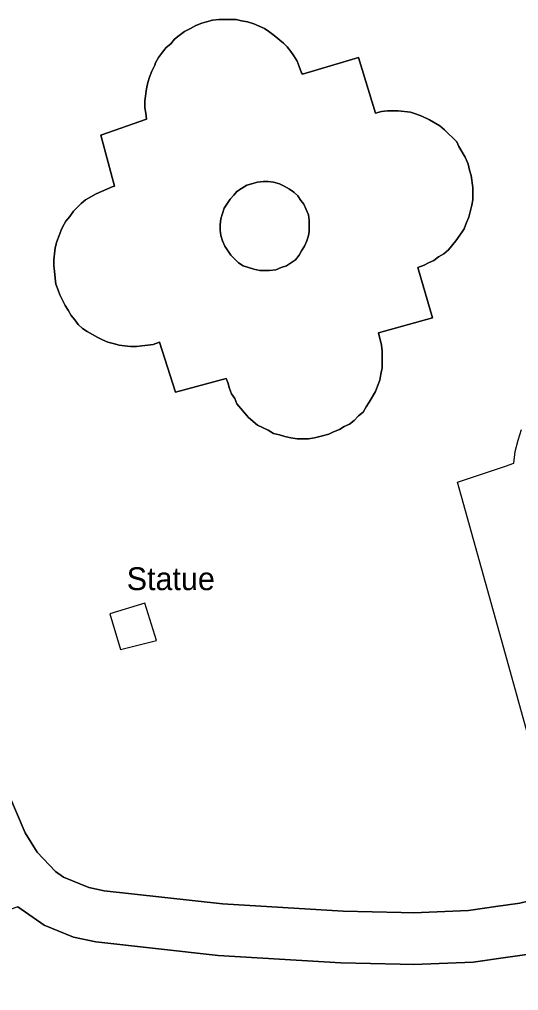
# Model space of a CAD drawing. Extents: x 529240 to 530363, y 179600 to 180767.
# Drawn here: x 529968 to 530000.9, y 180395.2 to 180459 of the extents above; entities that cross this region are included whole.
import ezdxf

# ---------------------------------------------------------------- set-up
doc = ezdxf.new("R2010")
doc.units = 0
for name, color, linetype in [('General surface', 7, 'Continuous'), ('Inland water', 7, 'Continuous'), ('Road Or Track', 7, 'Continuous'), ('Roadside', 7, 'Continuous'), ('Structure', 7, 'Continuous'), ('Unclassified', 7, 'Continuous')]:
    doc.layers.add(name, color=color, linetype=linetype)

msp = doc.modelspace()

# ---------------------------------------------------------------- linework, layer by layer
at = {"layer": 'General surface'}
for points in [[(529972.2, 180438.7), (529972.5, 180438.5), (529973.2, 180438.1), (529973.5, 180437.95), (529973.85, 180437.8), (529974.2, 180437.7), (529974.6, 180437.6), (529974.95, 180437.55), (529975.35, 180437.5), (529975.75, 180437.5), (529976.1, 180437.55), (529976.5, 180437.6), (529976.85, 180437.65), (529977.25, 180437.8), (529978.3, 180434.5), (529981.65, 180435.4), (529981.75, 180435.15), (529981.85, 180434.75), (529982, 180434.4), (529982.2, 180434.1), (529982.35, 180433.75), (529983.1, 180432.85), (529983.7, 180432.35), (529984.4, 180432), (529984.75, 180431.8), (529985.15, 180431.7), (529985.5, 180431.6), (529985.9, 180431.5), (529986.3, 180431.45), (529987.05, 180431.45), (529987.45, 180431.5), (529987.8, 180431.6), (529988.4, 180431.75), (529988.7, 180431.9), (529989.1, 180432.05), (529989.4, 180432.25), (529989.75, 180432.4), (529990.05, 180432.65), (529990.35, 180432.95), (529990.65, 180433.2), (529990.85, 180433.55), (529991.05, 180433.85), (529991.45, 180434.55), (529991.6, 180434.9), (529991.75, 180435.3), (529991.8, 180435.7), (529991.9, 180436.1), (529991.9, 180437.2), (529991.85, 180437.6), (529991.65, 180438.4), (529995.2, 180439.4), (529994.25, 180442.7), (529994.65, 180442.85), (529994.95, 180443), (529995.3, 180443.15), (529995.6, 180443.4), (529995.95, 180443.6), (529996.25, 180443.85), (529996.75, 180444.45), (529997.15, 180445.05), (529997.3, 180445.25), (529997.45, 180445.65), (529997.6, 180446), (529997.8, 180446.8), (529997.85, 180447.15), (529997.85, 180447.95), (529997.75, 180448.75), (529997.65, 180449.1), (529997.55, 180449.5), (529997.5, 180449.6), (529997.35, 180449.95), (529996.95, 180450.65), (529996.8, 180450.95), (529996, 180451.75), (529995.7, 180452), (529995, 180452.4), (529994.5, 180452.65), (529994.1, 180452.8), (529993.75, 180452.9), (529992.95, 180453), (529992.25, 180453), (529991.85, 180452.95), (529991.45, 180452.85), (529990.35, 180456.5), (529986.65, 180455.4), (529986.6, 180455.5), (529986.45, 180455.9), (529986.3, 180456.25), (529986.1, 180456.6), (529985.9, 180456.9), (529985.65, 180457.2), (529985.4, 180457.45), (529984.8, 180457.95), (529984.45, 180458.2), (529984.15, 180458.4), (529983.45, 180458.7), (529983.05, 180458.85), (529982.65, 180458.9), (529982.3, 180459), (529981.15, 180459), (529980.75, 180458.95), (529980.35, 180458.85), (529980.05, 180458.75), (529979.65, 180458.6), (529979.3, 180458.4), (529978.9, 180458.2), (529978.55, 180457.95), (529978.25, 180457.7), (529978, 180457.4), (529977.7, 180457.15), (529977.45, 180456.85), (529977.2, 180456.5), (529977, 180456.15), (529976.95, 180456), (529976.75, 180455.6), (529976.6, 180455.2), (529976.5, 180454.85), (529976.4, 180454.45), (529976.3, 180453.65), (529976.3, 180453.2), (529976.35, 180452.85), (529976.4, 180452.45), (529973.4, 180451.4), (529974.3, 180448.05), (529974.15, 180448), (529973.1, 180447.55), (529972.4, 180447.15), (529972.1, 180446.9), (529971.6, 180446.4), (529971.35, 180446.05), (529971.1, 180445.75), (529970.9, 180445.4), (529970.8, 180445.15), (529970.65, 180444.8), (529970.5, 180444.4), (529970.4, 180444), (529970.3, 180443.2), (529970.3, 180442.8), (529970.35, 180442.45), (529970.4, 180442), (529970.45, 180441.6), (529970.6, 180441.2), (529970.7, 180440.9), (529971.05, 180440.2), (529971.25, 180439.9), (529971.45, 180439.55), (529971.7, 180439.25), (529971.9, 180438.95)], [(529974.7, 180417.6), (529977.05, 180418.2), (529976.3, 180420.65), (529974, 180419.95)]]:
    msp.add_lwpolyline(points, close=True, dxfattribs=at)
msp.add_lwpolyline([(529967.34, 180408.07), (529968.42, 180405.55), (529969.21, 180404.28), (529970.41, 180403.02), (529970.95, 180402.64), (529972.61, 180401.96), (529973.61, 180401.75), (529981.4, 180400.88), (529989.33, 180400.4), (529993.15, 180400.32), (529993.96, 180400.3), (529997.57, 180400.45), (529999.52, 180400.73), (530000, 180400.79), (530000.94, 180400.92), (530004.59, 180401.8), (530010.32, 180403.48), (530037.41, 180411.44), (530041.45, 180412.83), (530045.29, 180414.53), (530047.93, 180416.01), (530048.93, 180416.58), (530052.35, 180418.91), (530058.82, 180424.09)], dxfattribs=at)
at = {"layer": 'Inland water'}
for points in [[(529971.9, 180438.95), (529972.2, 180438.7), (529972.5, 180438.5), (529973.2, 180438.1), (529973.5, 180437.95), (529973.85, 180437.8), (529974.2, 180437.7), (529974.6, 180437.6), (529974.95, 180437.55), (529975.35, 180437.5), (529975.75, 180437.5), (529976.1, 180437.55), (529976.5, 180437.6), (529976.85, 180437.65), (529977.25, 180437.8), (529978.3, 180434.5), (529981.65, 180435.4), (529981.75, 180435.15), (529981.85, 180434.75), (529982, 180434.4), (529982.2, 180434.1), (529982.35, 180433.75), (529983.1, 180432.85), (529983.7, 180432.35), (529984.4, 180432), (529984.75, 180431.8), (529985.15, 180431.7), (529985.5, 180431.6), (529985.9, 180431.5), (529986.3, 180431.45), (529987.05, 180431.45), (529987.45, 180431.5), (529987.8, 180431.6), (529988.4, 180431.75), (529988.7, 180431.9), (529989.1, 180432.05), (529989.4, 180432.25), (529989.75, 180432.4), (529990.05, 180432.65), (529990.35, 180432.95), (529990.65, 180433.2), (529990.85, 180433.55), (529991.05, 180433.85), (529991.45, 180434.55), (529991.6, 180434.9), (529991.75, 180435.3), (529991.8, 180435.7), (529991.9, 180436.1), (529991.9, 180437.2), (529991.85, 180437.6), (529991.65, 180438.4), (529995.2, 180439.4), (529994.25, 180442.7), (529994.65, 180442.85), (529994.95, 180443), (529995.3, 180443.15), (529995.6, 180443.4), (529995.95, 180443.6), (529996.25, 180443.85), (529996.75, 180444.45), (529997.15, 180445.05), (529997.3, 180445.25), (529997.45, 180445.65), (529997.6, 180446), (529997.8, 180446.8), (529997.85, 180447.15), (529997.85, 180447.95), (529997.75, 180448.75), (529997.65, 180449.1), (529997.55, 180449.5), (529997.5, 180449.6), (529997.35, 180449.95), (529996.95, 180450.65), (529996.8, 180450.95), (529996, 180451.75), (529995.7, 180452), (529995, 180452.4), (529994.5, 180452.65), (529994.1, 180452.8), (529993.75, 180452.9), (529992.95, 180453), (529992.25, 180453), (529991.85, 180452.95), (529991.45, 180452.85), (529990.35, 180456.5), (529986.65, 180455.4), (529986.6, 180455.5), (529986.45, 180455.9), (529986.3, 180456.25), (529986.1, 180456.6), (529985.9, 180456.9), (529985.65, 180457.2), (529985.4, 180457.45), (529984.8, 180457.95), (529984.45, 180458.2), (529984.15, 180458.4), (529983.45, 180458.7), (529983.05, 180458.85), (529982.65, 180458.9), (529982.3, 180459), (529981.15, 180459), (529980.75, 180458.95), (529980.35, 180458.85), (529980.05, 180458.75), (529979.65, 180458.6), (529979.3, 180458.4), (529978.9, 180458.2), (529978.55, 180457.95), (529978.25, 180457.7), (529978, 180457.4), (529977.7, 180457.15), (529977.45, 180456.85), (529977.2, 180456.5), (529977, 180456.15), (529976.95, 180456), (529976.75, 180455.6), (529976.6, 180455.2), (529976.5, 180454.85), (529976.4, 180454.45), (529976.3, 180453.65), (529976.3, 180453.2), (529976.35, 180452.85), (529976.4, 180452.45), (529973.4, 180451.4), (529974.3, 180448.05), (529974.15, 180448), (529973.1, 180447.55), (529972.4, 180447.15), (529972.1, 180446.9), (529971.6, 180446.4), (529971.35, 180446.05), (529971.1, 180445.75), (529970.9, 180445.4), (529970.8, 180445.15), (529970.65, 180444.8), (529970.5, 180444.4), (529970.4, 180444), (529970.3, 180443.2), (529970.3, 180442.8), (529970.35, 180442.45), (529970.4, 180442), (529970.45, 180441.6), (529970.6, 180441.2), (529970.7, 180440.9), (529971.05, 180440.2), (529971.25, 180439.9), (529971.45, 180439.55), (529971.7, 180439.25)], [(529981.3, 180445.9), (529981.5, 180446.6), (529981.9, 180447.2), (529982.15, 180447.45), (529982.35, 180447.7), (529982.65, 180447.9), (529983, 180448.1), (529983.7, 180448.3), (529984.1, 180448.35), (529984.4, 180448.35), (529984.75, 180448.3), (529985.15, 180448.2), (529985.45, 180448.05), (529985.8, 180447.85), (529986.1, 180447.65), (529986.35, 180447.4), (529986.55, 180447.1), (529986.75, 180446.85), (529987.05, 180446.15), (529987.1, 180445.8), (529987.1, 180445.05), (529987.05, 180444.8), (529986.95, 180444.45), (529986.8, 180444.1), (529986.6, 180443.8), (529986.45, 180443.5), (529986.2, 180443.2), (529985.6, 180442.8), (529985.25, 180442.7), (529984.9, 180442.55), (529984.5, 180442.5), (529983.85, 180442.5), (529983.45, 180442.6), (529982.75, 180442.8), (529982.45, 180443), (529981.95, 180443.5), (529981.55, 180444.1), (529981.4, 180444.45), (529981.3, 180444.8), (529981.25, 180445.15), (529981.25, 180445.5)]]:
    msp.add_lwpolyline(points, close=True, dxfattribs=at)
at = {"layer": 'Road Or Track'}
for points in [[(530011.94, 180392.6), (530010.83, 180400.08), (530005.47, 180398.51), (530001.74, 180397.61), (530000, 180397.36), (529997.88, 180397.06), (529993.99, 180396.9), (529993.08, 180396.92), (529989.19, 180397), (529981.11, 180397.49), (529973.06, 180398.39), (529971.61, 180398.7), (529969.67, 180399.49), (529967.94, 180400.68), (529960.36, 180398.03), (529960.2, 180397.67), (529959.26, 180397.81), (529957.55, 180398.06), (529954.48, 180398.5), (529953.23, 180394.13)], [(530010.83, 180400.08), (530005.47, 180398.51), (530001.74, 180397.61), (530000, 180397.36), (529997.88, 180397.06), (529993.99, 180396.9), (529993.08, 180396.92), (529989.19, 180397), (529981.11, 180397.49), (529973.06, 180398.39), (529971.61, 180398.7), (529969.67, 180399.49), (529967.94, 180400.68)]]:
    msp.add_lwpolyline(points, dxfattribs=at)
at = {"layer": 'Roadside'}
for points in [[(530058.82, 180424.09), (530052.35, 180418.91), (530048.93, 180416.58), (530047.93, 180416.01), (530045.29, 180414.53), (530041.45, 180412.83), (530037.41, 180411.44), (530010.32, 180403.48), (530004.59, 180401.8), (530000.94, 180400.92), (530000, 180400.79), (529999.52, 180400.73), (529997.57, 180400.45), (529993.96, 180400.3), (529993.15, 180400.32), (529989.33, 180400.4), (529981.4, 180400.88), (529973.61, 180401.75), (529972.61, 180401.96), (529970.95, 180402.64), (529970.41, 180403.02), (529969.21, 180404.28), (529968.42, 180405.55), (529967.34, 180408.07)], [(529967.94, 180400.68), (529969.67, 180399.49), (529971.61, 180398.7), (529973.06, 180398.39), (529981.11, 180397.49), (529989.19, 180397), (529993.08, 180396.92), (529993.99, 180396.9), (529997.88, 180397.06), (530000, 180397.36), (530001.74, 180397.61), (530005.47, 180398.51), (530010.83, 180400.08), (530038.44, 180408.2), (530042.7, 180409.66), (530046.81, 180411.49), (530049.6, 180413.05), (530050.73, 180413.69), (530054.45, 180416.23), (530054.52, 180416.29), (530061, 180421.48)]]:
    msp.add_lwpolyline(points, dxfattribs=at)
at = {"layer": 'Structure'}
for points in [[(529981.3, 180445.9), (529981.25, 180445.5), (529981.25, 180445.15), (529981.3, 180444.8), (529981.4, 180444.45), (529981.55, 180444.1), (529981.95, 180443.5), (529982.45, 180443), (529982.75, 180442.8), (529983.45, 180442.6), (529983.85, 180442.5), (529984.5, 180442.5), (529984.9, 180442.55), (529985.25, 180442.7), (529985.6, 180442.8), (529986.2, 180443.2), (529986.45, 180443.5), (529986.6, 180443.8), (529986.8, 180444.1), (529986.95, 180444.45), (529987.05, 180444.8), (529987.1, 180445.05), (529987.1, 180445.8), (529987.05, 180446.15), (529986.75, 180446.85), (529986.55, 180447.1), (529986.35, 180447.4), (529986.1, 180447.65), (529985.8, 180447.85), (529985.45, 180448.05), (529985.15, 180448.2), (529984.75, 180448.3), (529984.4, 180448.35), (529984.1, 180448.35), (529983.7, 180448.3), (529983, 180448.1), (529982.65, 180447.9), (529982.35, 180447.7), (529982.15, 180447.45), (529981.9, 180447.2), (529981.5, 180446.6)], [(529974, 180419.95), (529974.7, 180417.6), (529977.05, 180418.2), (529976.3, 180420.65)]]:
    msp.add_lwpolyline(points, close=True, dxfattribs=at)
at = {"layer": 'Unclassified'}
for points in [[(529971.9, 180438.95), (529971.7, 180439.25), (529971.45, 180439.55), (529971.25, 180439.9), (529971.05, 180440.2), (529970.7, 180440.9), (529970.6, 180441.2), (529970.45, 180441.6), (529970.4, 180442), (529970.35, 180442.45), (529970.3, 180442.8), (529970.3, 180443.2), (529970.4, 180444), (529970.5, 180444.4), (529970.65, 180444.8), (529970.8, 180445.15), (529970.9, 180445.4), (529971.1, 180445.75), (529971.35, 180446.05), (529971.6, 180446.4), (529972.1, 180446.9), (529972.4, 180447.15), (529973.1, 180447.55), (529974.15, 180448), (529974.3, 180448.05), (529973.4, 180451.4), (529976.4, 180452.45), (529976.35, 180452.85), (529976.3, 180453.2), (529976.3, 180453.65), (529976.4, 180454.45), (529976.5, 180454.85), (529976.6, 180455.2), (529976.75, 180455.6), (529976.95, 180456), (529977, 180456.15), (529977.2, 180456.5), (529977.45, 180456.85), (529977.7, 180457.15), (529978, 180457.4), (529978.25, 180457.7), (529978.55, 180457.95), (529978.9, 180458.2), (529979.3, 180458.4), (529979.65, 180458.6), (529980.05, 180458.75), (529980.35, 180458.85), (529980.75, 180458.95), (529981.15, 180459), (529982.3, 180459), (529982.65, 180458.9), (529983.05, 180458.85), (529983.45, 180458.7), (529984.15, 180458.4), (529984.45, 180458.2), (529984.8, 180457.95), (529985.4, 180457.45), (529985.65, 180457.2), (529985.9, 180456.9), (529986.1, 180456.6), (529986.3, 180456.25), (529986.45, 180455.9), (529986.6, 180455.5), (529986.65, 180455.4), (529990.35, 180456.5), (529991.45, 180452.85), (529991.85, 180452.95), (529992.25, 180453), (529992.95, 180453), (529993.75, 180452.9), (529994.1, 180452.8), (529994.5, 180452.65), (529995, 180452.4), (529995.7, 180452), (529996, 180451.75), (529996.8, 180450.95), (529996.95, 180450.65), (529997.35, 180449.95), (529997.5, 180449.6), (529997.55, 180449.5), (529997.65, 180449.1), (529997.75, 180448.75), (529997.85, 180447.95), (529997.85, 180447.15), (529997.8, 180446.8), (529997.6, 180446), (529997.45, 180445.65), (529997.3, 180445.25), (529997.15, 180445.05), (529996.75, 180444.45), (529996.25, 180443.85), (529995.95, 180443.6), (529995.6, 180443.4), (529995.3, 180443.15), (529994.95, 180443), (529994.65, 180442.85), (529994.25, 180442.7), (529995.2, 180439.4), (529991.65, 180438.4), (529991.85, 180437.6), (529991.9, 180437.2), (529991.9, 180436.1), (529991.8, 180435.7), (529991.75, 180435.3), (529991.6, 180434.9), (529991.45, 180434.55), (529991.05, 180433.85), (529990.85, 180433.55), (529990.65, 180433.2), (529990.35, 180432.95), (529990.05, 180432.65), (529989.75, 180432.4), (529989.4, 180432.25), (529989.1, 180432.05), (529988.7, 180431.9), (529988.4, 180431.75), (529987.8, 180431.6), (529987.45, 180431.5), (529987.05, 180431.45), (529986.3, 180431.45), (529985.9, 180431.5), (529985.5, 180431.6), (529985.15, 180431.7), (529984.75, 180431.8), (529984.4, 180432), (529983.7, 180432.35), (529983.1, 180432.85), (529982.35, 180433.75), (529982.2, 180434.1), (529982, 180434.4), (529981.85, 180434.75), (529981.75, 180435.15), (529981.65, 180435.4), (529978.3, 180434.5), (529977.25, 180437.8), (529976.85, 180437.65), (529976.5, 180437.6), (529976.1, 180437.55), (529975.75, 180437.5), (529975.35, 180437.5), (529974.95, 180437.55), (529974.6, 180437.6), (529974.2, 180437.7), (529973.85, 180437.8), (529973.5, 180437.95), (529973.2, 180438.1), (529972.5, 180438.5), (529972.2, 180438.7), (529971.9, 180438.95)], [(529981.3, 180445.9), (529981.5, 180446.6), (529981.9, 180447.2), (529982.15, 180447.45), (529982.35, 180447.7), (529982.65, 180447.9), (529983, 180448.1), (529983.7, 180448.3), (529984.1, 180448.35), (529984.4, 180448.35), (529984.75, 180448.3), (529985.15, 180448.2), (529985.45, 180448.05), (529985.8, 180447.85), (529986.1, 180447.65), (529986.35, 180447.4), (529986.55, 180447.1), (529986.75, 180446.85), (529987.05, 180446.15), (529987.1, 180445.8), (529987.1, 180445.05), (529987.05, 180444.8), (529986.95, 180444.45), (529986.8, 180444.1), (529986.6, 180443.8), (529986.45, 180443.5), (529986.2, 180443.2), (529985.6, 180442.8), (529985.25, 180442.7), (529984.9, 180442.55), (529984.5, 180442.5), (529983.85, 180442.5), (529983.45, 180442.6), (529982.75, 180442.8), (529982.45, 180443), (529981.95, 180443.5), (529981.55, 180444.1), (529981.4, 180444.45), (529981.3, 180444.8), (529981.25, 180445.15), (529981.25, 180445.5), (529981.3, 180445.9)], [(530003.45, 180404.9), (530000, 180417.3), (529996.85, 180428.6), (530000, 180429.65), (530000.55, 180429.85), (530000.65, 180430.6), (530000.85, 180431.35), (530001.05, 180432.05)], [(529967.34, 180408.07), (529968.42, 180405.55), (529969.21, 180404.28), (529970.41, 180403.02), (529970.95, 180402.64), (529972.61, 180401.96), (529973.61, 180401.75), (529981.4, 180400.88), (529989.33, 180400.4), (529993.15, 180400.32), (529993.96, 180400.3), (529997.57, 180400.45), (529999.52, 180400.73), (530000, 180400.79), (530000.94, 180400.92), (530004.59, 180401.8), (530010.32, 180403.48), (530037.41, 180411.44), (530041.45, 180412.83), (530045.29, 180414.53), (530047.93, 180416.01), (530048.93, 180416.58), (530052.35, 180418.91), (530058.82, 180424.09)], [(529974, 180419.95), (529974.7, 180417.6), (529977.05, 180418.2), (529976.3, 180420.65), (529974, 180419.95)]]:
    msp.add_lwpolyline(points, dxfattribs=at)

# ---------------------------------------------------------------- texts
at = {"layer": 'Structure'}
msp.add_text('Statue', height=1.5, dxfattribs=at).set_placement((529975.1, 180421.5))

doc.saveas('drawing.dxf')
